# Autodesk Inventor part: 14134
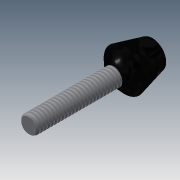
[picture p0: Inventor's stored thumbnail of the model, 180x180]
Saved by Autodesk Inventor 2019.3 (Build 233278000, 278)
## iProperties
Created: 2012-01
Part Number: 14134
Material: Ogólny
Document SubType Name: Modeling
Designer: CADENGINEERING4
Density: 1 g/cm^3
Appearance: Domyślna
Author: CADENGINEERING4
Revision Number: ÈÎºÎ
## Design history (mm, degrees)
feature "NONE"
node "Bryła1"
